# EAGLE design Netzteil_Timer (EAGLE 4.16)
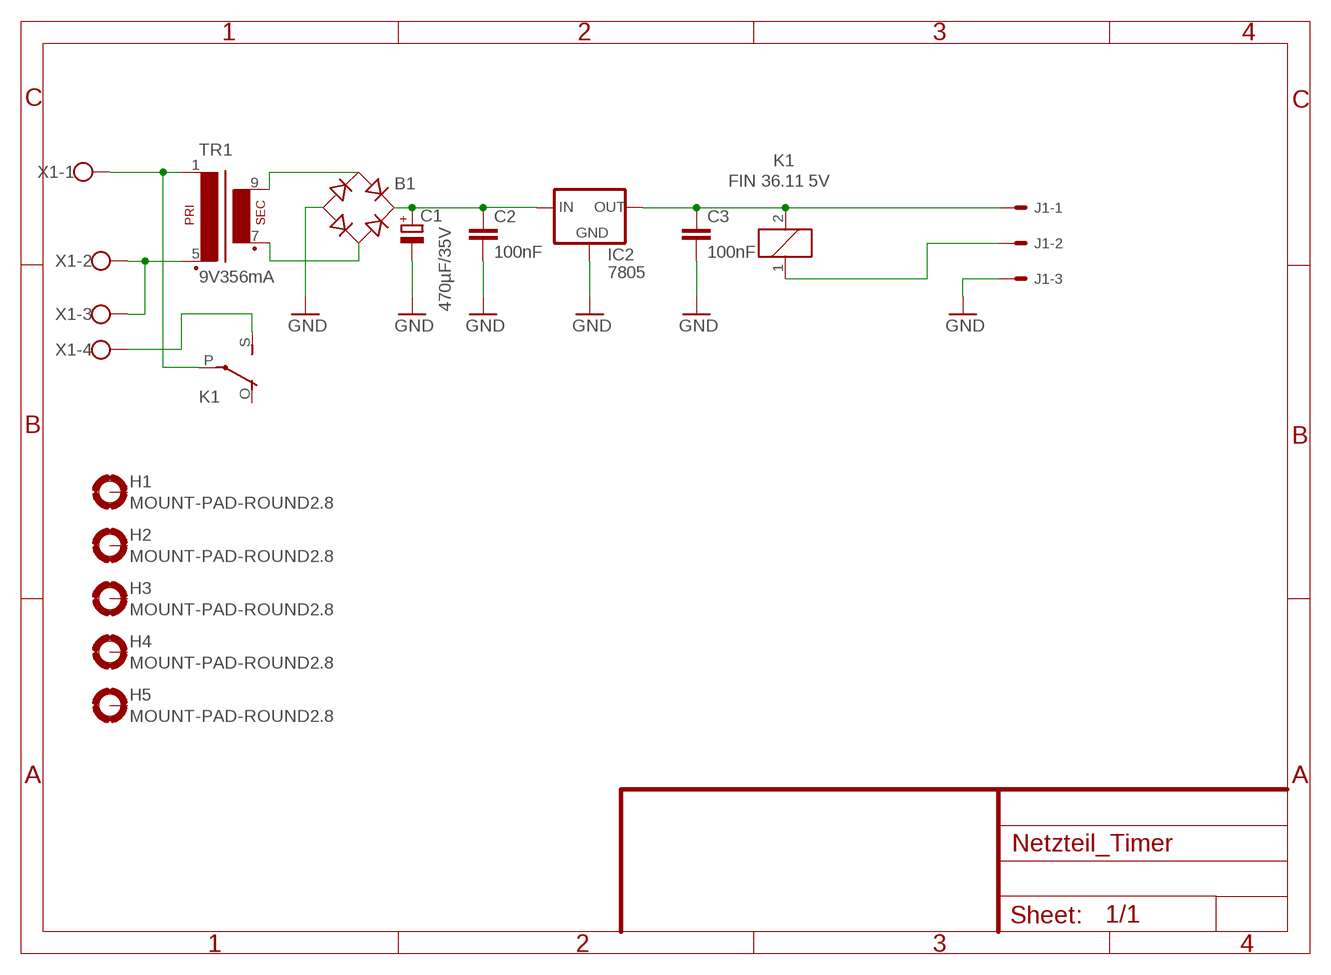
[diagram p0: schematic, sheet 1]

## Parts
B1  B-DIL  [B-DIL]
C1  470µF/35V  CPOL-EUE5-13  [E5-13]
C2  100nF  C-EU050-024X044  [C050-024X044]
C3  100nF  C-EU050-024X044  [C050-024X044]
H1  MOUNT-PAD-ROUND2.8  [2,8-PAD]
H2  MOUNT-PAD-ROUND2.8  [2,8-PAD]
H3  MOUNT-PAD-ROUND2.8  [2,8-PAD]
H4  MOUNT-PAD-ROUND2.8  [2,8-PAD]
H5  MOUNT-PAD-ROUND2.8  [2,8-PAD]
IC2  7805  78XXL  [78XXL]
J1  22-27-2031-03  [6410-03]
K1  FIN 36.11 5V  G5L  [G5LE]
TR1  9V356mA  EI38-1  [EI38-1]
X1  W237-4  [W237-4]

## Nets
GND: B1.- C1.- C2.2 C3.2 IC2.GND J1.3
N$1: B1.AC1 TR1.9
N$2: B1.AC2 TR1.7
N$3: B1.+ C1.+ C2.1 IC2.IN
N$4: C3.1 IC2.OUT J1.1 K1.2
N$5: K1.P(2:P) TR1.1 X1.1
N$6: TR1.5 X1.2 X1.3
N$8: J1.2 K1.1
N$9: K1.S(2:S) X1.4
Unconnected: H1.B2,8(MOUNT) H2.B2,8(MOUNT) H3.B2,8(MOUNT) H4.B2,8(MOUNT) H5.B2,8(MOUNT) K1.O(2:O)

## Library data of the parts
B1 = rectifier:B-DIL: RECTIFIER
C1 = rcl:CPOL-EU: POLARIZED CAPACITOR, European symbol
C2 C3 = rcl:C-EU: CAPACITOR, European symbol
H1-H5 = holes:MOUNT-PAD-ROUND: MOUNTING PAD, round
IC2 = v-reg:78XXL: VOLTAGE REGULATOR
J1 = ep_molex_6410_7395-02:22-?-03: CONNECTOR wire to board 2.54 mm (.1 inch) pitch header
K1 = relay:G5L: RELAY 1 x switch, 10 A/120 V AC, 8 A/30 V ADC, Omron
TR1 = trafo:EI38-1: TRANSFORMER 1 primary winding, 1 secondary winding ERA
X1 = con-wago-500:W237-4: WAGO SCREW CLAMP

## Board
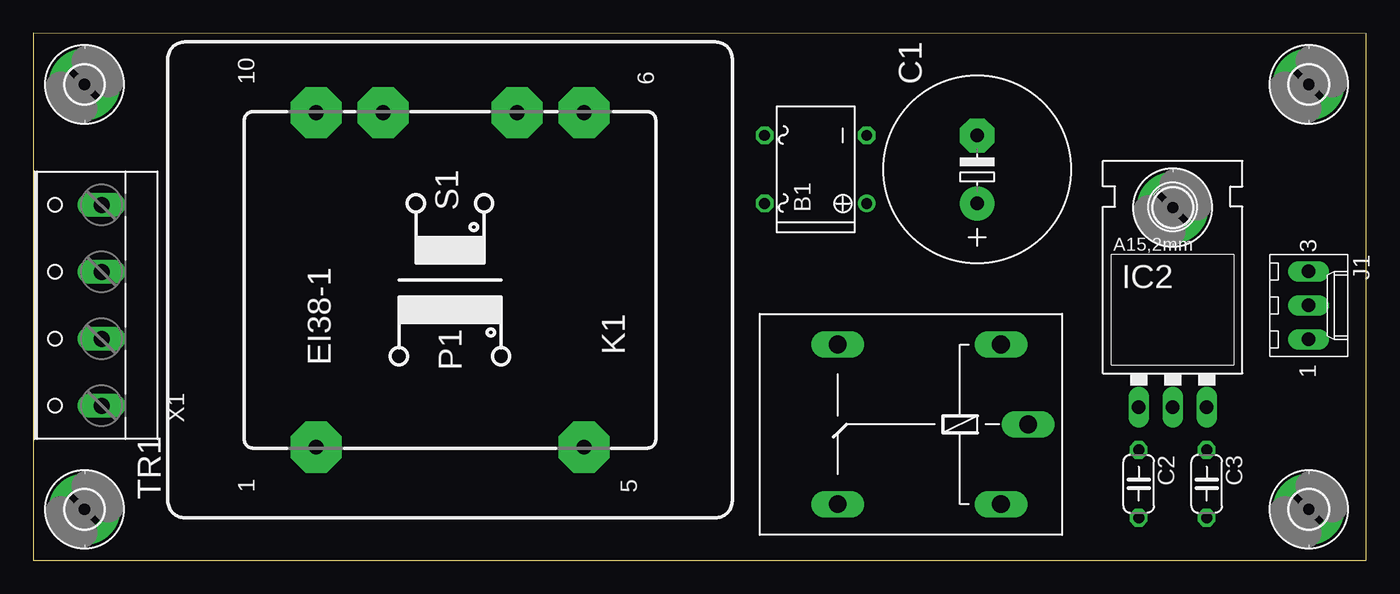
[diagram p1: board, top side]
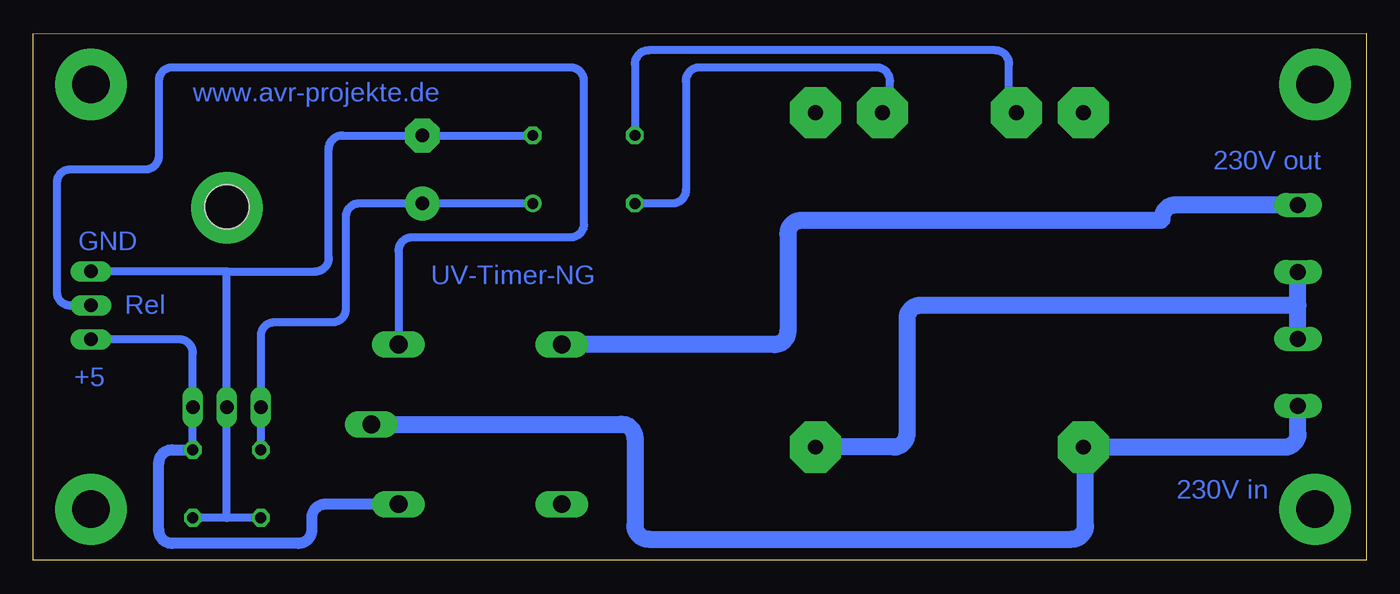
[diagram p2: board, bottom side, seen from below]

Size 99.53 x 39.37 mm. Coordinates in mm from the lower left corner, seen from the top.
Outline: 0,0 99.53,0.01 99.53,39.37 0,39.37 0,0
Copper layers (1*16): Top 0.035mm / dielectric 1.5mm / Bottom 0.035mm
Design rules "default": minimum track width 10mil, minimum drill 0.4mm, track to track 10mil, track to pad 10mil, pad to pad 10mil, via to via 10mil, smd to smd 10mil, copper to edge 40mil, drill to drill 8mil, minimum pad ring 10mil, minimum via ring 0.3mm, stop-mask expansion 4mil, vias tented up to drill 0mil, thermal gap 10mil
bKeepout: area 0,0 to 12.7,29.2; area 12.7,2.5 to 71.1,22.9

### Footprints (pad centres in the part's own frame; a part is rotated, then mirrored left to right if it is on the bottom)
B-DIL = drill 0.813 round: + -2.54,-3.81 | drill 0.813 octagon: - 2.54,-3.81; AC1 2.54,3.81; AC2 -2.54,3.81
E5-13 = drill 1.016 pad 2.54 round: + -2.54,0 | drill 1.016 pad 2.54 octagon: - 2.54,0
C050-024X044 = drill 0.813 octagon: 1 -2.54,0; 2 2.54,0
2,8-PAD = drill 2.8 pad 5.334 round: B2,8 0,0
78XXL = drill 1.016 long: GND 0,-3.81; IN -2.54,-3.81; OUT 2.54,-3.81 | hole 3.302: 0,11.176
6410-03 = drill 1.016 long: 1 2.54,0; 2 0,0; 3 -2.54,0
G5LE = drill 1.321 long: 1 -7.493,-5.969; 2 -7.493,5.969; O 4.699,5.969; P -9.525,0; S 4.699,-5.969
EI38-1 = drill 1.118 pad 3.81 octagon: 1 -12.497,10.008; 5 -12.497,-10.008; 6 12.497,-10.008; 7 12.497,-5.004; 9 12.497,5.004; 10 12.497,10.008
W237-4 = drill 1.194 long: 1 -7.5,-1.27; 2 -2.5,-1.27; 3 2.5,-1.27; 4 7.5,-1.27

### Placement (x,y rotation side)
B1  58.42,29.21 90 top
C1  70.48,29.21 90 top
C2  82.55,5.71 270 top
C3  87.63,5.71 270 top
H1  3.81,3.81 0 top
H2  3.81,35.56 0 top
H3  95.25,35.56 0 top
H4  95.25,3.81 0 top
H5  85.09,26.35 0 top
IC2  85.09,15.24 0 top
J1  95.25,19.05 270 top
K1  64.77,10.16 180 top
TR1  31.11,20.95 90 top
X1  3.81,19.05 90 top

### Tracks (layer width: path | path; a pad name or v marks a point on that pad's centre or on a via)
GND
  Bottom 0.61: B1.- C1.- 76.47,31.75 arc-90 77.47,30.75 77.47,22.59 arc90 78.47,21.59 85.09,21.59 | 85.09,21.59 IC2.GND 85.09,3.17 | 85.09,21.59 J1.3 | 85.09,3.17 C2.2 82.55,3.44 | 85.09,3.17 C3.2
N$1
  Bottom 0.61: TR1.9 26.67,33.45 26.67,37.1 arc-90 27.67,38.1 53.61,38.1 arc-90 54.61,37.1 B1.AC1
N$2
  Bottom 0.61: TR1.7 35.56,33.45 35.56,35.83 arc-90 36.56,36.83 49.8,36.83 arc-90 50.8,35.83 50.8,27.67 arc90 51.8,26.67 B1.AC2
N$3
  Bottom 0.61: B1.+ 69.85,26.67 | 69.85,26.67 C1.+ | 69.85,26.67 75.2,26.67 arc-90 76.2,25.67 76.2,18.78 arc90 77.2,17.78 81.55,17.78 arc-90 82.55,16.78 IC2.IN C2.1
N$4
  Bottom 0.61: C3.1 IC2.OUT 87.63,15.51 arc-90 88.63,16.51 J1.1
  Bottom 0.813: K1.2 77.74,4.19 arc-90 78.74,3.19 78.74,2.27 arc90 79.74,1.27 89.17,1.27 arc90 90.17,2.27 90.17,7.25 arc90 89.17,8.26 C3.1
N$5
  Bottom 1.27: X1.1 5.08,9.46 arc90 6.08,8.46 TR1.1 20.95,8.46 20.95,2.59 arc90 21.95,1.59 53.61,1.59 arc90 54.61,2.59 54.61,9.16 arc-90 55.61,10.16 K1.P
N$6
  Bottom 1.27: 5.08,16.51 X1.2 5.08,19.05 | 5.08,19.05 X1.3 | 5.08,19.05 33.29,19.05 arc-90 34.29,18.05 34.29,9.46 arc90 35.29,8.46 TR1.5
N$8
  Bottom 0.61: K1.1 72.26,23.13 arc90 71.26,24.13 59.42,24.13 arc-90 58.42,25.13 58.42,35.83 arc-90 59.42,36.83 89.17,36.83 arc-90 90.17,35.83 90.17,30.21 arc90 91.17,29.21 96.79,29.21 arc-90 97.79,28.21 97.79,20.05 arc-90 96.79,19.05 J1.2
N$9
  Bottom 1.27: X1.4 14.24,26.55 arc-90 15.24,25.55 arc90 15.39,25.4 42.18,25.4 arc-90 43.18,24.4 43.18,17.13 arc90 44.18,16.13 K1.S

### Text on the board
Bottom: www.avr-projekte.de | 230V out | GND | UV-Timer-NG | Rel | +5 | 230V in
